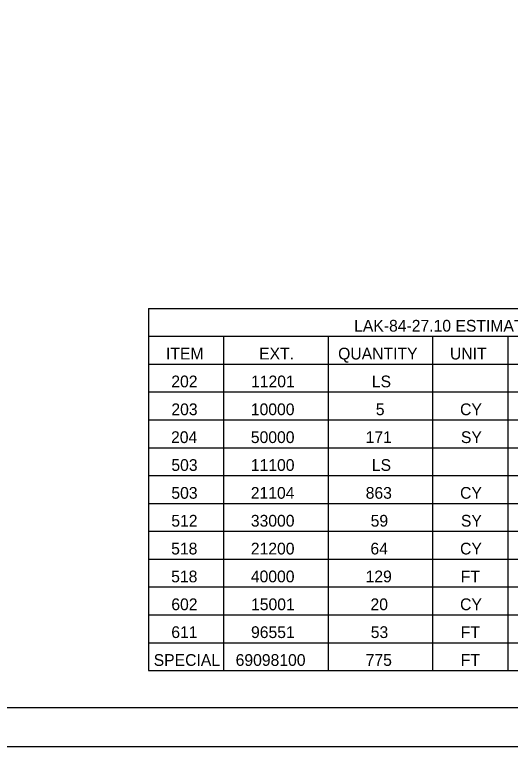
# Model space of a CAD drawing. Extents: x 0 to 34, y 0 to 22.
# Drawn here: x 17.24 to 23.65, y 0 to 9.46 of the extents above; entities that cross this region are included whole.
import ezdxf

# ---------------------------------------------------------------- set-up
doc = ezdxf.new("R2010")
doc.units = 0
for name, color, linetype in [('SH_Border', 7, 'Continuous'), ('SH_Cut_Line', 7, 'Continuous'), ('SH_Text', 7, 'Continuous')]:
    doc.layers.add(name, color=color, linetype=linetype)

msp = doc.modelspace()

# ---------------------------------------------------------------- linework, layer by layer
at = {"layer": 'SH_Border'}
msp.add_lwpolyline([(1.5, 21.5), (33.5, 21.5), (33.5, 0.5), (1.5, 0.5)], close=True, dxfattribs=at)
at = {"layer": 'SH_Cut_Line'}
msp.add_lwpolyline([(0, 0), (34, 0), (34, 22), (0, 22)], close=True, dxfattribs=at)
at = {"layer": 'SH_Text'}
for p, q in [((18.968, 5.66), (31.1, 5.66)), ((18.968, 5.66), (18.968, 0.98)), ((18.968, 5.3), (31.1, 5.3)), ((19.94, 5.3), (19.94, 0.98)), ((21.29, 5.3), (21.29, 0.98)), ((22.64, 5.3), (22.64, 0.98)), ((23.612, 5.3), (23.612, 0.98)), ((18.968, 4.94), (31.1, 4.94)), ((18.968, 4.58), (31.1, 4.58)), ((18.968, 4.22), (31.1, 4.22)), ((18.968, 3.86), (31.1, 3.86)), ((18.968, 3.5), (31.1, 3.5)), ((18.968, 3.14), (31.1, 3.14)), ((18.968, 2.78), (31.1, 2.78)), ((18.968, 2.42), (31.1, 2.42)), ((18.968, 2.06), (31.1, 2.06)), ((18.968, 1.7), (31.1, 1.7)), ((18.968, 1.34), (31.1, 1.34)), ((18.968, 0.98), (31.1, 0.98))]:
    msp.add_line(p, q, dxfattribs=at)

# ---------------------------------------------------------------- texts
for s, p in [('LAK-84-27.10 ESTIMATED QUANTITIES (CARRIED TO SHEET P.144)', (21.627, 5.36)), ('ITEM', (19.1958, 5)), ('EXT.', (20.3989, 5)), ('QUANTITY', (21.4205, 5)), ('UNIT', (22.8652, 5)), ('202', (19.2649, 4.64)), ('11201', (20.2949, 4.64)), ('LS', (21.8561, 4.64)), ('203', (19.2656, 4.28)), ('10000', (20.2923, 4.28)), ('5', (21.9071, 4.28)), ('CY', (22.9962, 4.28)), ('204', (19.2614, 3.92)), ('50000', (20.2923, 3.92)), ('171', (21.7757, 3.92)), ('SY', (23.0069, 3.92)), ('503', (19.2656, 3.56)), ('11100', (20.2923, 3.56)), ('LS', (21.8561, 3.56)), ('503', (19.2656, 3.2)), ('21104', (20.2916, 3.2)), ('863', (21.7766, 3.2)), ('CY', (22.9962, 3.2)), ('512', (19.2649, 2.84)), ('33000', (20.2923, 2.84)), ('59', (21.8407, 2.84)), ('SY', (23.0069, 2.84)), ('518', (19.263, 2.48)), ('21200', (20.2923, 2.48)), ('64', (21.8378, 2.48)), ('CY', (22.9962, 2.48)), ('518', (19.263, 2.12)), ('40000', (20.2923, 2.12)), ('129', (21.7753, 2.12)), ('FT', (23.0047, 2.12)), ('602', (19.2649, 1.76)), ('15001', (20.2949, 1.76)), ('20', (21.8386, 1.76)), ('CY', (22.9962, 1.76)), ('611', (19.2647, 1.4)), ('96551', (20.2949, 1.4)), ('53', (21.842, 1.4)), ('FT', (23.0047, 1.4)), ('SPECIAL', (19.0371, 1.04)), ('69098100', (20.0961, 1.04)), ('775', (21.7763, 1.04)), ('FT', (23.0047, 1.04))]:
    msp.add_text(s, height=0.1518, dxfattribs=at).set_placement(p)

doc.saveas('drawing.dxf')
